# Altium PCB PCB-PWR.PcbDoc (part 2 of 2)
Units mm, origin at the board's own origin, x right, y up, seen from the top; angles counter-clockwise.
Board outline 90 x 60 mm, 4 copper layers (F.Cu, In1.Cu, In2.Cu, B.Cu); 66 components, 31 nets, 210 pads, 267 vias.
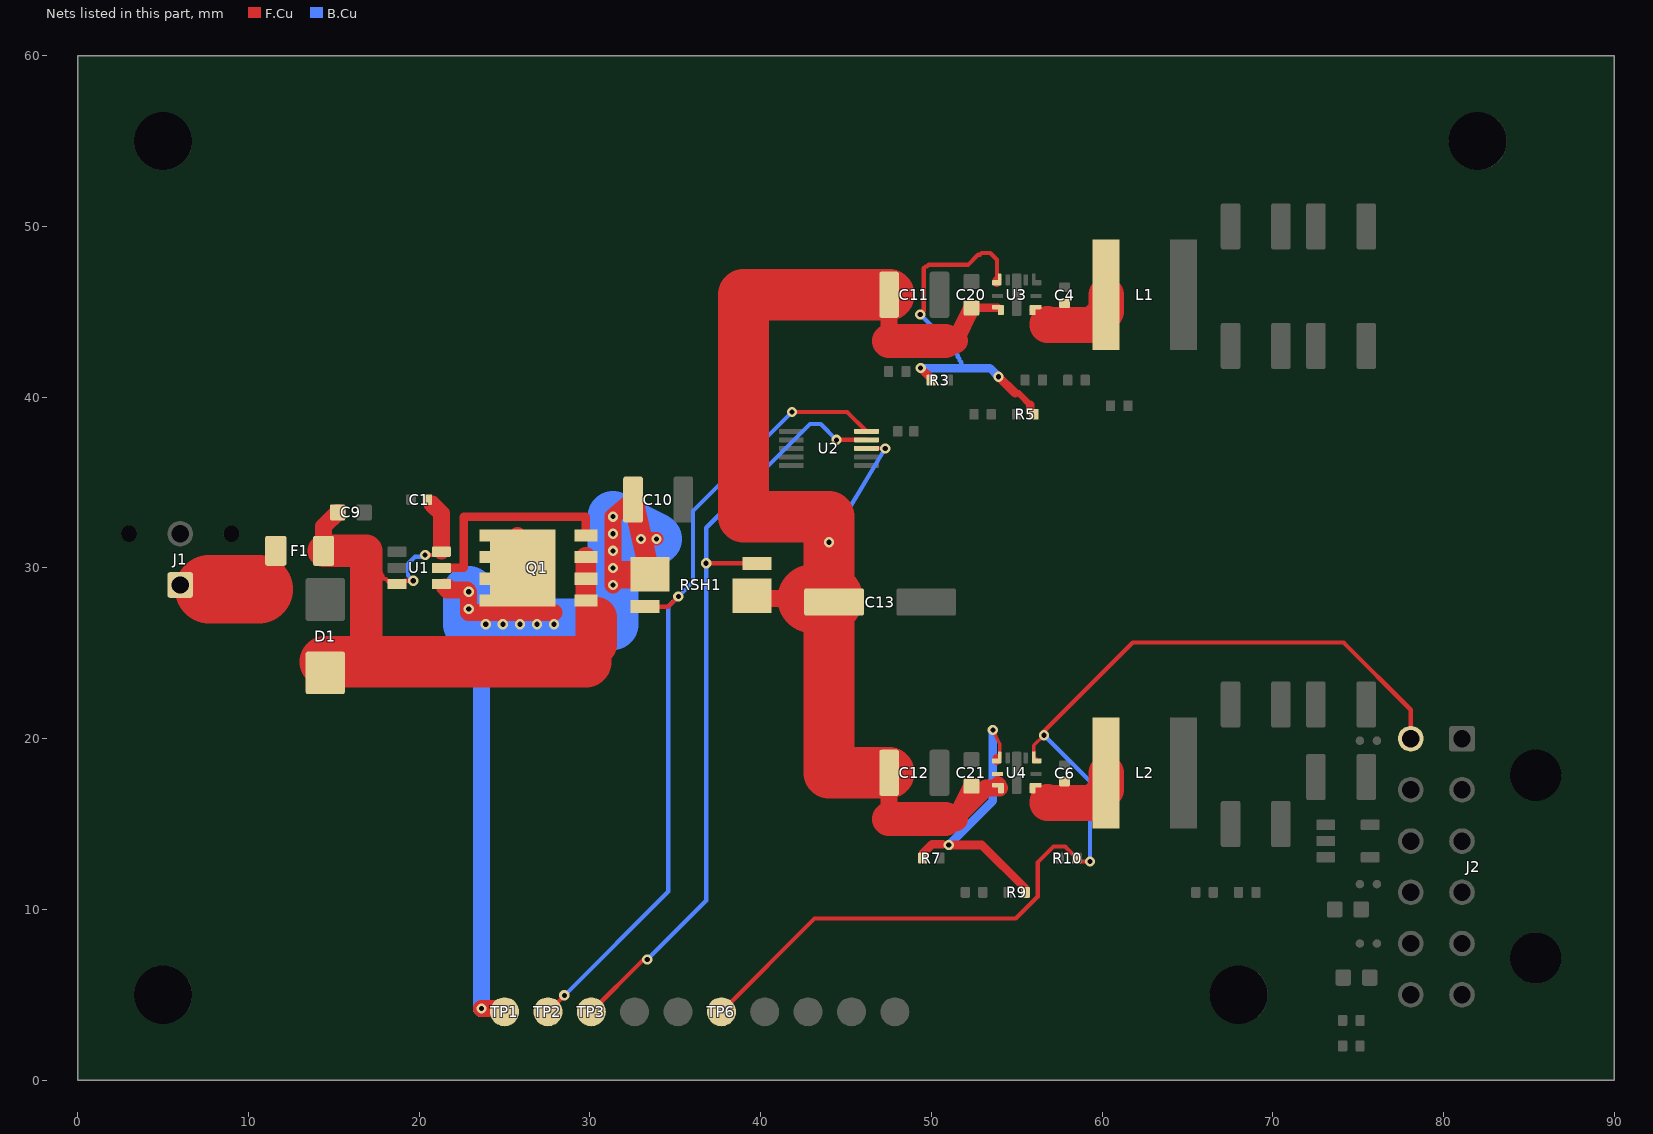
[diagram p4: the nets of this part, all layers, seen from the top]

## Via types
v1: diameter 0.6, hole 0.3, F.Cu to B.Cu, tented both sides, 267 vias

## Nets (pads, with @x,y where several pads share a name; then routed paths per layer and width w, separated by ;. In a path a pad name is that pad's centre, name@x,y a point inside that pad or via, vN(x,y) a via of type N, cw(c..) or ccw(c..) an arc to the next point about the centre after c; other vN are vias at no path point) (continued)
PWR_GOOD: J2.7 R10.2 TP6.1 U4.5 | length 64.7
  F.Cu w0.2: U4.5@56,19.1 56,19.6 v1(56.6,20.2)
  F.Cu w0.201: U4.5@56,19.1 U4.5@56,18.9 56.01,18.9 U4.5@56.112,18.798
  F.Cu w0.25: TP6.1@37.7,4 43.16,9.46 54.944,9.46 56.225,10.741 56.225,12.751 57.149,13.676 57.834,13.676 R10.2@58.51,13 58.71,12.8 v1(59.296,12.8) ; U4.5@56.112,18.798 56.175,18.735 U4.5@56.175,18.7 ; v1(56.6,20.2) 56.6,20.429 61.797,25.627 74.148,25.627 78.08,21.695 J2.7@78.08,20
  B.Cu w0.25: v1(56.6,20.2) 59.296,17.504 v1(59.296,12.8)
REV_GATE: Q1.4 U1.5 | length 12.6
  F.Cu w0.5: U1.5@21.3,30 22.6,30 22.6,33 29.77,33 Q1.4@29.77,31.905
RT_3V3: R7.1 R9.2 U4.8 | length 17.6
  F.Cu w0.2: v1(53.6,20.5) 54,19.7 U4.8@54,19.1
  F.Cu w0.201: 53.825,18.86 53.865,18.9 U4.8@54,18.9 U4.8@54,19.1
  F.Cu w0.375: 50.667,13.81 50.707,13.771 v1(51.018,13.771) v1(51.018,13.771)
  F.Cu w0.5: R7.1@49.49,13 49.49,13.256 50.045,13.81 50.667,13.81 ; v1(51.018,13.771) 52.953,13.771 55.51,11.214 R9.2@55.51,11 ; U4.8@53.825,18.7 53.825,18.86
  B.Cu w0.5: v1(51.018,13.771) 53.6,16.353 v1(53.6,20.5)
RT_3V8: R3.1 R5.2 U3.8 | length 22.1
  F.Cu w0.201: 53.825,46.86 53.865,46.9 U3.8@54,46.9
  F.Cu w0.25: v1(49.35,44.85) 49.55,45.05 49.55,47.55 49.65,47.65 49.75,47.65 49.85,47.75 52.15,47.75 52.75,48.35 52.85,48.35 52.95,48.45 53.45,48.45 53.85,48.05 53.85,46.95
  F.Cu w0.375: 54.909,40.229 55.114,40.229 55.8,39.543
  F.Cu w0.5: v1(49.372,41.705) 49.99,41.088 R3.1@49.99,41 ; U3.8@53.825,46.7 53.825,46.86 ; v1(53.939,41.199) 54.909,40.229 ; 55.8,39.543 55.8,39.21 R5.2@56.01,39
  B.Cu w0.25: v1(49.35,44.85) 51.35,42.85 51.35,42.75 51.45,42.65 51.45,42.55 51.55,42.45 51.55,42.35 51.65,42.25 51.65,42.15 51.75,42.05 51.75,41.85 51.85,41.75
  B.Cu w0.5: v1(49.372,41.705) 53.433,41.705 v1(53.939,41.199)
SHUNT_LOAD_SENSE: RSH1.4 TP3.1 U2.9 | length 46.5
  F.Cu w0.25: TP3.1@30.08,4 33.147,7.067 v1(33.362,7.067) ; v1(36.811,30.27) RSH1.4@39.78,30.27 ; v1(44.45,37.5) U2.9@46.2,37.5
  B.Cu w0.25: v1(33.362,7.067) 36.811,10.516 v1(36.811,30.27) 36.811,32.351 42.887,38.427 43.523,38.427 v1(44.45,37.5)
SHUNT_SOURCE_SENSE: RSH1.3 TP2.1 U2.10 | length 48.1
  F.Cu w0.25: TP2.1@27.54,4 v1(28.504,4.964) ; RSH1.3@33.22,27.73 34.397,27.73 34.59,27.73 v1(35.18,28.32) ; v1(41.841,39.132) 45.067,39.132 U2.10@46.2,38
  B.Cu w0.25: v1(28.504,4.964) 34.59,11.05 34.59,27.73 v1(35.18,28.32) 36.043,29.183 36.043,33.335 v1(41.841,39.132)
SW_3V3: C6.2 L2.1 U4.3 | length 6
  F.Cu w0.251: U4.3@56.086,17.013 56.75,16.35
  F.Cu w0.346: U4.3@55.927,17.1 56,17.1 U4.3@56.086,17.013
  F.Cu w0.561: 56.75,16.349 56.8,16.3
  F.Cu w2.1: 56.8,16.3 56.8,16.22 59.45,16.22 60.24,17.01 L2.1@60.24,18
SW_3V8: C4.2 L1.1 U3.3 | length 6
  F.Cu w0.251: U3.3@56.086,45.013 56.75,44.35
  F.Cu w0.346: U3.3@55.927,45.1 56,45.1 U3.3@56.086,45.013
  F.Cu w0.561: 56.75,44.349 56.8,44.3
  F.Cu w2.1: 56.8,44.3 56.8,44.22 59.45,44.22 60.24,45.01 L1.1@60.24,46
VBAT_FUSED: C1.2 C9.1 D1.1 F1.2 Q1.1 Q1.2 Q1.3 U1.3 U1.6 | length 45.9
  F.Cu w0.25: 17.25,30.25 17.75,29.75 17.75,29.65 17.85,29.55 17.85,29.45 17.95,29.35 18.05,29.35 18.25,29.15 U1.3@18.35,29.15 ; U1.3@19.05,29.15 19.15,29.25 v1(19.65,29.25) ; v1(20.35,30.75) 20.85,30.75 U1.6@20.95,30.85
  F.Cu w0.561: C1.2@20.48,34 C1.2@20.749,33.731
  F.Cu w0.601: U1.6@21.3,30.95 U1.6@21.3,31.002
  F.Cu w1: F1.2@14.4,31 14.4,32.425 C9.1@15.225,33.25 ; D1.1@14.5,23.85 15.15,24.5 16.9,24.5 ; C1.2@20.749,33.731 21.3,33.18 U1.6@21.3,31.002
  F.Cu w1.2: 29.77,24.5 Q1.3@29.77,30.635
  F.Cu w1.9: F1.2@14.4,31 16.9,31 16.9,24.5
  F.Cu w2.4: 30.4,25.5 30.4,27.1
  F.Cu w3: D1.1@14.5,24.5 29.77,24.5
  B.Cu w0.25: v1(19.65,29.25) 19.35,29.55 19.35,30.25 19.75,30.65 20.25,30.65 v1(20.35,30.75)
VBAT_PROTECTED: C10.1 Q1.5 Q1.6 Q1.7 Q1.8 RSH1.1 TP1.1 U1.4 | length 70.8
  F.Cu w0.601: U1.4@21.3,29.05 U1.4@21.471,28.879 ; 21.643,28.707 U1.4@21.643,28.879
  F.Cu w0.8: v1(33,31.7) v1(33.9,31.7)
  F.Cu w1: U1.4@21.471,28.879 U1.4@21.643,28.879 ; 21.643,28.707 22.793,28.707 v1(22.9,28.6) 22.9,27.4 27.9,27.4 ; v1(23.646,4.2) 24.8,4.2 TP1.1@25,4 ; Q1.8@25.764,28.095 25.764,28.435 Q1.5@26.059,28.73 26.059,29.07 Q1.7@25.764,29.365 25.764,29.705 Q1.5@26.059,30 25.764,30.295 Q1.6@25.764,30.635 26.059,30.93 Q1.5@26.059,31.27 25.764,31.565 Q1.5@25.764,31.905 ; v1(31.35,29) v1(31.35,33) C10.1@32.525,34 ; v1(31.35,30) v1(31.35,31) ; RSH1.1@32.6,29.6 33.48,29.6 RSH1.1@33.515,29.635
  F.Cu w1.2: C10.1@32.525,34 RSH1.1@33.515,29.635
  F.Cu w1.6: 31.85,29.6 RSH1.1@32.6,29.6
  B.Cu w1: v1(23.646,4.2) 23.646,26.446 v1(23.9,26.7) ; v1(31.35,31) v1(31.35,32)
  B.Cu w3: v1(22.9,28.6) 22.9,26.7 31.35,26.7 v1(31.35,33) v1(33.9,31.7)
  other v1: 24.9,26.7 25.9,26.7 26.9,26.7 27.9,26.7 22.9,27.6
VBAT_RAW: F1.1 J1.1 | length 7.4
  F.Cu w1: J1.1@6,29 6.25,28.75 7.7,28.75 ; 10.6,28.75 11.6,29.75 F1.1@11.6,31
  F.Cu w4: 7.7,28.75 10.6,28.75
VBAT_SYS: C11.1 C12.1 C13.1 C20.1 C21.1 RSH1.2 U2.8 U3.1 U4.1 U4.9 | length 82.6
  F.Cu w0.2: U2.8@46.2,37 v1(47.3,37)
  F.Cu w0.25: U4.9@53.875,17.925 U4.1@53.9,17.25
  F.Cu w0.251: U3.1@53.897,45.275 U3.1@54.073,45.1
  F.Cu w0.346: U4.1@53.998,17.1 U4.1@54.073,17.1
  F.Cu w0.5: C21.1@52.35,17.225 U4.1@53.9,17.25 ; C20.1@52.35,45.225 U3.1@53.9,45.25
  F.Cu w1: RSH1.2@39.485,28.365 39.65,28.2 40,28.2 C13.1@43,28.2 ; C13.1@44,28.2 44.2,28 C13.1@44.3,28 ; 47.525,15.3 C12.1@47.525,18 ; 47.525,43.3 C11.1@47.525,46 ; 51.4,43.3 C20.1@52.35,45.225 ; C21.1@52.35,17.225 51.4,15.3 53.2,17.1 53.897,17.1 ; U4.1@53.897,17.275 53.897,17.1 ; U4.1@53.998,17.1 53.897,17.1
  F.Cu w1.5: 50.8,15.3 51.4,15.3 ; 50.8,43.3 51.4,43.3
  F.Cu w2: 47.525,15.3 50.8,15.3 ; 47.525,43.3 50.8,43.3
  F.Cu w3: C12.1@47.525,18 44,18 44,28.2 44,33 39,33 39,46 C11.1@47.525,46
  F.Cu w4: C13.1@43,28.2 C13.1@44,28.2
  B.Cu w0.25: v1(44,31.5) v1(47.3,37)
pads on no net: H1.Un1 H2.Un1 H3.Un1 H4.Un1 J1.Un1 J1.Un2 J2.Un1 J2.Un2 Q1.Un1 Q1.Un2 Q1.Un3 Q1.Un4 Q1.Un5 Q1.Un6 Q1.Un7 Q1.Un8 Q1.Un9 Q1.Un10 Q1.Un11 Q1.Un12 Q1.Un13 Q1.Un14 Q1.Un15 Q1.Un16 U3.Un1 U3.Un2 U3.Un3 U3.Un4 U3.Un5 U3.Un6 U3.Un7 U4.Un1 U4.Un2 U4.Un3 U4.Un4 U4.Un5 U4.Un6 U4.Un7 U5.4

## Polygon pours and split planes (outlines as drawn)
GND_PWR on F.Cu "F.Cu-GND_PWR" (solid, remove dead copper, pour order 52): 0.45,59.55 89.55,59.55 89.55,0.45 0.45,0.45
GND_MODEM on F.Cu "F.Cu-GND_MODEM" (solid, remove dead copper, pour order 42): 73.603,20.483 73.227,19.957 73.079,19.543 73.05,19.25 73.05,18.195 72.879,17.743 72.85,17.45 72.879,17.157 72.964,16.876 73.103,16.617 73.289,16.389 73.517,16.203 73.776,16.064 74.057,15.979 74.35,15.95 74.643,15.979 75.057,16.127 75.302,16.29 75.71,16.698 75.936,17.076 76.043,17.503 76.05,18.653 76.373,19.143 76.485,19.415 76.55,19.85 76.521,20.143 76.436,20.424 76.297,20.683 76.002,21.009 75.624,21.236 75.197,21.343 74.757,21.321 74.343,21.173 73.989,20.911
GND_DIGITAL on F.Cu "F.Cu-GND_DIGITAL" (solid, remove dead copper, pour order 40): 75.8,13.6 82.6,13.6 82.6,9.6 75.8,9.6
VBAT_RAW on F.Cu "F.Cu-VBAT_RAW" (solid, remove dead copper, pour order 48): 13.146,28.481 13.448,28.985 13.59,29.554 13.6,31 13.514,31.581 13.263,32.111 12.869,32.546 12.365,32.848 11.796,32.99 11.404,32.99 11.019,32.914 10.657,32.764 10.186,32.414 9.836,31.943 9.686,31.581 9.61,31.196 9.6,30.75 6.966,30.75 6.581,30.914 6,31 5.419,30.914 4.889,30.663 4.454,30.269 4.152,29.765 4.01,29.196 4.01,28.804 4.086,28.419 4.236,28.057 4.454,27.731 4.836,27.336 5.139,27.087 5.669,26.836 6.054,26.76 10.6,26.75 10.99,26.788 11.543,26.986 11.869,27.204
VBAT_SYS on F.Cu "F.Cu-VBAT_SYS-1" (solid, remove dead copper, pour order 51): 152 vertices, not listed, extent 37,13.3 56.072,48
3V3_DIGITAL on F.Cu "F.Cu-3V3_DIGITAL-3" (solid, remove dead copper, pour order 36): 49.447,38.633 49.261,38.861 49.033,39.047 48.635,39.235 48.347,39.293 48.053,39.293 47.765,39.235 47.493,39.123 47.248,38.96 47.041,38.752 46.814,38.374 46.707,37.947 46.7,37.5 46.053,37.493 45.626,37.386 45.367,37.247 45.139,37.061 44.877,36.707 44.729,36.293 44.707,35.853 44.814,35.426 45.04,35.048 45.248,34.84 45.493,34.677 45.765,34.565 46.053,34.507 47.847,34.507 48.274,34.614 48.652,34.84 49.359,35.548 49.586,35.926 49.671,36.207 49.7,36.5 49.693,37.947 49.586,38.374
3V8_MODEM on F.Cu "F.Cu-3V8_MODEM-1" (solid, remove dead copper, pour order 39): 49.029,9.425 48.757,9.537 48.322,9.602 47.15,9.602 46.714,9.537 46.316,9.349 45.99,9.053 45.764,8.676 45.678,8.394 45.657,7.955 45.764,7.528 45.99,7.15 46.198,6.942 46.576,6.716 46.857,6.63 47.7,6.602 47.912,6.39 47.895,3.948 34.793,3.948 33.681,5.061 33.453,5.247 33.055,5.435 32.62,5.5 32.185,5.435 31.913,5.323 31.668,5.159 31.373,4.833 31.185,4.435 31.127,4.147 31.127,3.853 31.185,3.565 31.297,3.293 31.461,3.048 33.111,1.387 33.339,1.201 33.598,1.062 34.025,0.955 48.516,0.948 48.952,1.012 49.224,1.125 49.468,1.288 50.571,2.392 50.798,2.769 50.883,3.051 50.912,3.343 50.912,7.012 50.847,7.447 50.659,7.845 50.472,8.072 49.382,9.162
VBAT_FUSED on F.Cu "F.Cu-VBAT_FUSED" (solid, remove dead copper, pour order 44): 12.552,33.19 12.41,32.621 12.4,31 12.438,30.61 12.636,30.057 12.854,29.731 13.131,29.454 13.635,29.152 14.204,29.01 14.9,29 14.9,26.5 14.11,26.462 13.735,26.348 13.389,26.163 13.086,25.914 12.837,25.611 12.652,25.265 12.538,24.89 12.5,24.5 12.529,24.175 12.51,23.654 12.652,23.085 12.837,22.739 13.086,22.436 13.389,22.187 13.735,22.002 14.304,21.86 14.89,21.888 15.443,22.086 15.769,22.304 15.978,22.5 29.966,22.51 30.351,22.586 30.713,22.736 31.184,23.086 31.534,23.557 31.699,23.982 32.063,24.389 32.248,24.735 32.39,25.304 32.39,27.296 32.314,27.681 32.164,28.043 31.946,28.369 31.77,28.554 31.77,30.635 31.732,31.025 31.534,31.578 31.316,31.904 30.881,32.298 30.535,32.483 30.16,32.597 29.77,32.635 29.38,32.597 29.005,32.483 28.659,32.298 28.356,32.049 28.107,31.746 27.922,31.4 27.808,31.025 27.77,30.635 27.77,26.5 18.9,26.5 18.9,27.157 19.246,27.16 19.672,27.251 20.04,27.288 20.415,27.402 20.761,27.587 21.064,27.836 21.313,28.139 21.498,28.485 21.618,28.903 22.243,29.186 22.569,29.404 22.846,29.681 23.148,30.185 23.262,30.56 23.3,30.95 23.29,33.376 23.214,33.761 23.064,34.123 22.714,34.594 21.749,35.546 21.423,35.764 21.061,35.914 20.676,35.99 20.284,35.99 19.899,35.914 19.369,35.663 19.066,35.414 18.817,35.111 18.632,34.765 18.518,34.39 18.49,33.804 18.632,33.235 18.817,32.889 19.239,32.413 18.936,32.164 18.697,31.874 18.446,32.269 18.011,32.663 17.665,32.848 17.204,32.974 17.215,33.446 17.139,33.831 16.888,34.361 16.639,34.664 16.168,35.014 15.615,35.212 15.225,35.25 14.835,35.212 14.46,35.098 14.114,34.913 13.811,34.664 12.986,33.839 12.737,33.536
3V3_DIGITAL on F.Cu "F.Cu-3V3_DIGITAL-2" (solid, remove dead copper, pour order 35): 56.832,21.633 56.537,21.959 56.159,22.186 55.732,22.293 55.438,22.293 55.011,22.186 54.633,21.959 54.425,21.752 54.199,21.374 54.114,21.093 54.085,20.8 54.085,18.875 54.114,18.582 54.199,18.301 54.425,17.923 54.633,17.715 55.011,17.489 55.292,17.404 55.585,17.375 55.878,17.404 56.159,17.489 56.418,17.628 56.646,17.814 56.832,18.042 56.971,18.301 57.056,18.582 57.085,18.875 57.085,20.8 57.02,21.235
3V3_DIGITAL on F.Cu "F.Cu-3V3_DIGITAL-1" (solid, remove dead copper, pour order 34): 207 vertices, not listed, extent 55.99,0.507 75.59,26.493
VBAT_PROTECTED on F.Cu "F.Cu-VBAT_PROTECTED-1" (solid, remove dead copper, pour order 47): 26.069,5.746 25.743,5.964 25.381,6.114 24.8,6.2 23.646,6.2 23.256,6.162 22.881,6.048 22.535,5.863 22.232,5.614 21.983,5.311 21.798,4.965 21.684,4.59 21.646,4.2 21.684,3.81 21.798,3.435 21.983,3.089 22.232,2.786 22.535,2.537 22.881,2.352 23.256,2.238 23.646,2.2 24.133,2.2 24.61,2.038 25,2 25.581,2.086 26.111,2.337 26.546,2.731 26.764,3.057 26.914,3.419 27,4 26.914,4.581 26.764,4.943 26.546,5.269
VBAT_PROTECTED on F.Cu "F.Cu-VBAT_PROTECTED" (solid, remove dead copper, pour order 46): 27.427,33.016 27.178,33.319 26.875,33.568 26.345,33.819 25.764,33.905 25.183,33.819 24.821,33.669 24.35,33.319 24.101,33.016 23.916,32.67 23.774,32.101 23.764,31.565 23.821,31.1 23.774,30.831 23.764,30.454 23.558,30.555 23.183,30.669 22.449,30.707 21.881,30.964 21.496,31.04 21.104,31.04 20.719,30.964 20.189,30.713 19.886,30.464 19.637,30.161 19.452,29.815 19.338,29.44 19.3,29.05 19.338,28.66 19.452,28.285 19.637,27.939 19.886,27.636 20.374,27.161 20.7,26.943 20.986,26.821 21.136,26.457 21.486,25.986 21.957,25.636 22.319,25.486 22.9,25.4 27.9,25.4 28.29,25.438 28.665,25.552 29.011,25.737 29.446,26.131 29.664,26.457 29.814,26.819 29.89,27.204 29.883,27.644 30.239,27.337 30.769,27.086 31.35,27 31.74,27.038 32.293,27.236 32.619,27.454 32.777,27.6 33.676,27.61 34.245,27.752 34.591,27.937 34.894,28.186 35.094,28.408 35.279,28.692 35.444,29.106 35.51,29.492 35.499,29.884 35.397,30.377 35.664,30.757 35.862,31.31 35.9,31.7 35.814,32.281 35.664,32.643 35.446,32.969 35.169,33.246 34.68,33.541 34.428,34.615 34.352,34.814 34.168,35.141 33.901,35.451 33.436,35.78 33.071,35.924 32.668,35.995 32.1,35.954 31.711,35.827 31.229,35.523 30.054,34.523 29.781,34.241 29.586,33.943 29.436,33.581 29.356,33.16 29.367,28.756 29.169,28.946 28.843,29.164 28.481,29.314 28.03,29.394 28.002,29.535 28.059,30 28.002,30.465 28.049,30.734 28.059,31.27 28.021,31.66 27.907,32.035 27.695,32.418 27.612,32.67
3V8_MODEM on F.Cu "F.Cu-3V8_MODEM" (solid, remove dead copper, pour order 38): 152 vertices, not listed, extent 54.05,18.507 85,54.7
VBAT_SYS on F.Cu "F.Cu-VBAT_SYS" (solid, remove dead copper, pour order 50): 48.243,35.236 48.569,35.454 48.963,35.889 49.214,36.419 49.29,36.804 49.262,37.39 49.148,37.765 48.846,38.269 48.569,38.546 48.065,38.848 47.69,38.962 47.3,39 46.004,38.99 45.619,38.914 45.257,38.764 44.931,38.546 44.654,38.269 44.436,37.943 44.286,37.581 44.21,37.196 44.21,36.804 44.286,36.419 44.436,36.057 44.654,35.731 44.931,35.454 45.435,35.152 46.004,35.01 47.496,35.01 47.881,35.086
3V3_DIGITAL on F.Cu "F.Cu-3V3_DIGITAL" (solid, remove dead copper, pour order 33): 62.833,40.207 62.669,40.452 62.343,40.747 61.945,40.935 61.657,40.993 61.363,40.993 60.936,40.886 60.677,40.747 60.35,40.452 60.124,40.074 60.039,39.793 60.01,39.5 60.017,38.453 60.075,38.165 60.187,37.893 60.35,37.648 60.558,37.44 60.803,37.277 61.075,37.165 61.363,37.107 61.657,37.107 61.945,37.165 62.217,37.277 62.462,37.44 62.669,37.648 62.896,38.026 63.003,38.453 63.003,39.647 62.945,39.935
VBAT_FUSED on B.Cu "B.Cu-VBAT_FUSED" (solid, remove dead copper, pour order 43): 21.664,29.236 22.013,29.639 22.264,30.169 22.35,30.75 22.312,31.14 22.114,31.693 21.896,32.019 21.461,32.413 21.115,32.598 20.74,32.712 20.35,32.75 19.36,32.612 18.985,32.498 18.481,32.196 17.936,31.664 17.687,31.361 17.502,31.015 17.388,30.64 17.35,30.25 17.36,29.354 17.502,28.785 17.687,28.439 17.936,28.136 18.381,27.704 18.885,27.402 19.454,27.26 19.846,27.26 20.415,27.402 20.761,27.587 21.064,27.836 21.414,28.307 21.564,28.669
3V3_DIGITAL on B.Cu "B.Cu-3V3_DIGITAL-2" (solid, remove dead copper, pour order 32): 84.421,22.293 84.336,22.574 84.197,22.833 83.902,23.159 83.524,23.386 83.097,23.493 76.5,23.5 76.207,23.471 75.866,23.359 71.366,21.259 71.113,21.109 70.894,20.913 70.647,20.548 70.517,20.128 70.515,19.688 70.641,19.266 70.791,19.013 70.987,18.794 71.222,18.617 71.487,18.49 71.772,18.417 72.066,18.401 72.357,18.443 72.634,18.541 76.833,20.5 81.45,20.5 81.45,16.22 80.141,15.17 79.931,14.964 79.701,14.589 79.612,14.309 79.58,14.017 79.606,13.724 79.688,13.441 79.91,13.061 80.115,12.851 80.49,12.621 80.771,12.532 81.063,12.5 81.356,12.526 81.639,12.608 81.899,12.744 83.902,14.34 84.197,14.667 84.38,15.049 84.45,15.483 84.45,22
3V8_MODEM on B.Cu "B.Cu-3V8_MODEM" (solid, remove dead copper, pour order 37): 65.574,24.158 65.16,24.01 64.898,23.831 53.326,23.831 53.034,23.802 52.753,23.717 52.375,23.49 46.089,17.215 45.902,16.987 45.764,16.728 45.678,16.447 45.65,16.154 45.65,8.102 45.678,7.809 45.764,7.528 45.99,7.15 46.198,6.942 46.576,6.716 47.003,6.609 47.297,6.609 47.724,6.716 47.983,6.854 48.309,7.15 48.472,7.395 48.585,7.666 48.65,8.102 48.65,15.533 53.948,20.831 65.51,20.831 65.946,20.896 66.24,21.022 69.906,17.367 70.15,17.204 70.422,17.091 70.857,17.026 79.607,17.026 79.899,17.055 80.314,17.204 80.667,17.466 82.24,19.048 82.403,19.293 82.515,19.565 82.58,20 82.551,20.293 82.466,20.574 82.24,20.952 82.032,21.16 81.654,21.386 81.373,21.471 81.08,21.5 80.645,21.435 80.247,21.247 80.019,21.061 78.985,20.027 71.479,20.027 67.757,23.748 67.53,23.934 67.27,24.073 66.843,24.18 65.867,24.187
VBAT_SYS on B.Cu "B.Cu-VBAT_SYS" (solid, remove dead copper, pour order 49): 42.285,32.529 42.06,31.987 42.002,31.599 42.022,31.207 42.192,30.646 42.393,30.309 42.656,30.019 42.971,29.785 43.325,29.617 43.706,29.522 44.097,29.502 44.673,29.617 45.027,29.784 45.342,30.017 45.715,30.471 49.015,35.971 49.183,36.325 49.298,36.901 49.24,37.485 49.108,37.854 48.783,38.342 48.492,38.606 48.156,38.808 47.787,38.94 47.399,38.997 47.007,38.978 46.627,38.883 46.273,38.716 45.958,38.482 45.585,38.029
VBAT_PROTECTED on B.Cu "B.Cu-VBAT_PROTECTED" (solid, remove dead copper, pour order 45): 33.548,29.731 34.135,29.714 34.518,29.798 35.043,30.059 35.47,30.461 35.762,30.971 35.869,31.348 35.886,31.935 35.733,32.501 35.421,32.999 35.138,33.27 34.808,33.482 32.115,34.848 31.74,34.962 31.311,35 30.96,34.962 30.732,34.902 30.407,34.764 30.207,34.641 29.936,34.414 29.78,34.238 29.568,33.908 29.436,33.581 29.381,33.352 29.35,33 29.35,28.7 24.895,28.7 24.862,28.99 24.748,29.365 24.563,29.711 24.314,30.014 23.843,30.364 23.481,30.514 23.096,30.59 22.51,30.562 21.957,30.364 21.486,30.014 21.237,29.711 21.052,29.365 20.91,28.796 20.91,26.504 20.986,26.119 21.136,25.757 21.354,25.431 21.646,25.143 21.656,4.004 21.798,3.435 22.1,2.931 22.377,2.654 22.881,2.352 23.45,2.21 23.842,2.21 24.227,2.286 24.757,2.537 25.192,2.931 25.41,3.257 25.56,3.619 25.636,4.004 25.646,24.7 31.546,24.71 31.931,24.786 32.461,25.037 32.764,25.286 33.013,25.589 33.198,25.935 33.312,26.31 33.35,26.7 33.35,29.777
GND_PWR on B.Cu "B.Cu-GND_PWR" (solid, remove dead copper, pour order 53): 0.45,59.55 89.55,59.55 89.55,0.45 0.45,0.45
GND_MODEM on B.Cu "B.Cu-GND_MODEM" (solid, remove dead copper, pour order 41): 76.624,18.836 76.197,18.943 74.35,18.95 73.915,18.885 73.517,18.697 73.289,18.511 73.103,18.283 72.964,18.024 72.879,17.743 72.85,17.45 72.879,17.157 72.964,16.876 73.103,16.617 73.398,16.29 73.643,16.127 73.915,16.015 74.35,15.95 75.429,15.95 76.389,14.989 76.617,14.803 77.076,14.564 77.515,14.415 77.803,14.357 78.797,14.357 79.224,14.464 79.811,14.76 80.257,14.927 81.257,15.427 81.611,15.689 81.873,16.043 81.985,16.315 82.043,16.603 82.043,16.897 81.985,17.185 81.873,17.457 81.709,17.702 81.502,17.909 81.257,18.073 80.985,18.185 80.697,18.243 80.157,18.221 79.876,18.136 79.089,17.74 78.776,17.636 78.275,17.388 78.219,17.402 77.002,18.61
3V3_DIGITAL on B.Cu "B.Cu-3V3_DIGITAL-1" (solid, remove dead copper, pour order 31): 56.259,11.243 56.561,10.922 56.808,10.764 57.082,10.656 57.372,10.605 57.666,10.61 58.091,10.726 58.464,10.959 58.753,11.291 58.933,11.692 58.985,11.982 58.98,12.276 57.012,21.263 56.894,21.532 56.726,21.774 56.394,22.063 55.993,22.243 55.703,22.295 55.409,22.29 55.122,22.227 54.853,22.109 54.611,21.941 54.407,21.729 54.249,21.481 54.141,21.208 54.09,20.918 54.095,20.624 56.025,11.779 56.116,11.499
3V3_DIGITAL on B.Cu "B.Cu-3V3_DIGITAL" (solid, remove dead copper, pour order 30): 62.945,39.035 62.833,39.307 62.669,39.552 62.343,39.847 62.084,39.986 61.657,40.093 61.363,40.093 61.075,40.035 60.803,39.923 60.558,39.759 60.35,39.552 60.187,39.307 60.075,39.035 60.01,38.6 60.01,37.5 47.7,37.5 47.407,37.471 47.126,37.386 46.867,37.247 46.639,37.061 46.453,36.833 46.314,36.574 46.229,36.293 46.2,36 46.229,35.707 46.377,35.293 46.639,34.939 46.993,34.677 47.265,34.565 47.553,34.507 60.887,34.5 63,32.38 63,25 63.065,24.565 63.253,24.167 63.439,23.939 63.667,23.753 63.926,23.614 64.207,23.529 64.5,23.5 64.793,23.529 65.074,23.614 65.333,23.753 65.659,24.048 65.886,24.426 65.993,24.853 65.993,33.147 65.886,33.574 65.659,33.952 63.01,36.62 63.01,38.6
GND_PWR on In1.Cu "In1.Cu-GND_PWR-2" (solid, remove dead copper, pour order 29): 49.8,47.6 55.35,47.6 55.35,44.4 49.8,44.4
GND_PWR on In1.Cu "In1.Cu-GND_PWR-1" (solid, remove dead copper, pour order 28): 49.8,19.6 55.35,19.6 55.35,16.4 49.8,16.4
GND_PWR on In1.Cu "In1.Cu-GND_PWR" (solid, remove dead copper, pour order 54): 0.45,59.55 89.55,59.55 89.55,0.45 0.45,0.45
GND_PWR on In2.Cu "In2.Cu-GND_PWR" (solid, remove dead copper, pour order 55): 0.45,59.55 89.55,59.55 89.55,0.45 0.45,0.45

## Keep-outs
F.Cu:
  region: 82.78,58.923 83.531,58.696 84.222,58.326 84.828,57.828 85.326,57.222 85.696,56.531 85.923,55.78 86,55 85.923,54.22 85.696,53.469 85.326,52.778 84.828,52.172 84.222,51.674 83.531,51.304 82.78,51.077 82,51 81.22,51.077 80.469,51.304 79.778,51.674 79.172,52.172 78.674,52.778 78.304,53.469 78.077,54.22 78,55 78.077,55.78 78.304,56.531 78.674,57.222 79.172,57.828 79.778,58.326 80.469,58.696 81.22,58.923 82,59
  region: 5.78,8.923 6.531,8.696 7.222,8.326 7.828,7.828 8.326,7.222 8.696,6.531 8.923,5.78 9,5 8.923,4.22 8.696,3.469 8.326,2.778 7.828,2.172 7.222,1.674 6.531,1.304 5.78,1.077 5,1 4.22,1.077 3.469,1.304 2.778,1.674 2.172,2.172 1.674,2.778 1.304,3.469 1.077,4.22 1,5 1.077,5.78 1.304,6.531 1.674,7.222 2.172,7.828 2.778,8.326 3.469,8.696 4.22,8.923 5,9
  region: 68.78,8.923 69.531,8.696 70.222,8.326 70.828,7.828 71.326,7.222 71.696,6.531 71.923,5.78 72,5 71.923,4.22 71.696,3.469 71.326,2.778 70.828,2.172 70.222,1.674 69.531,1.304 68.78,1.077 68,1 67.22,1.077 66.469,1.304 65.778,1.674 65.172,2.172 64.674,2.778 64.304,3.469 64.077,4.22 64,5 64.077,5.78 64.304,6.531 64.674,7.222 65.172,7.828 65.778,8.326 66.469,8.696 67.22,8.923 68,9
  region: 5.78,58.923 6.531,58.696 7.222,58.326 7.828,57.828 8.326,57.222 8.696,56.531 8.923,55.78 9,55 8.923,54.22 8.696,53.469 8.326,52.778 7.828,52.172 7.222,51.674 6.531,51.304 5.78,51.077 5,51 4.22,51.077 3.469,51.304 2.778,51.674 2.172,52.172 1.674,52.778 1.304,53.469 1.077,54.22 1,55 1.077,55.78 1.304,56.531 1.674,57.222 2.172,57.828 2.778,58.326 3.469,58.696 4.22,58.923 5,59
  region: 76.1,10.78 75.1,10.78 75.1,11.18 76.1,11.18
In1.Cu:
  region: 82.78,58.923 83.531,58.696 84.222,58.326 84.828,57.828 85.326,57.222 85.696,56.531 85.923,55.78 86,55 85.923,54.22 85.696,53.469 85.326,52.778 84.828,52.172 84.222,51.674 83.531,51.304 82.78,51.077 82,51 81.22,51.077 80.469,51.304 79.778,51.674 79.172,52.172 78.674,52.778 78.304,53.469 78.077,54.22 78,55 78.077,55.78 78.304,56.531 78.674,57.222 79.172,57.828 79.778,58.326 80.469,58.696 81.22,58.923 82,59
  region: 5.78,8.923 6.531,8.696 7.222,8.326 7.828,7.828 8.326,7.222 8.696,6.531 8.923,5.78 9,5 8.923,4.22 8.696,3.469 8.326,2.778 7.828,2.172 7.222,1.674 6.531,1.304 5.78,1.077 5,1 4.22,1.077 3.469,1.304 2.778,1.674 2.172,2.172 1.674,2.778 1.304,3.469 1.077,4.22 1,5 1.077,5.78 1.304,6.531 1.674,7.222 2.172,7.828 2.778,8.326 3.469,8.696 4.22,8.923 5,9
  region: 68.78,8.923 69.531,8.696 70.222,8.326 70.828,7.828 71.326,7.222 71.696,6.531 71.923,5.78 72,5 71.923,4.22 71.696,3.469 71.326,2.778 70.828,2.172 70.222,1.674 69.531,1.304 68.78,1.077 68,1 67.22,1.077 66.469,1.304 65.778,1.674 65.172,2.172 64.674,2.778 64.304,3.469 64.077,4.22 64,5 64.077,5.78 64.304,6.531 64.674,7.222 65.172,7.828 65.778,8.326 66.469,8.696 67.22,8.923 68,9
  region: 5.78,58.923 6.531,58.696 7.222,58.326 7.828,57.828 8.326,57.222 8.696,56.531 8.923,55.78 9,55 8.923,54.22 8.696,53.469 8.326,52.778 7.828,52.172 7.222,51.674 6.531,51.304 5.78,51.077 5,51 4.22,51.077 3.469,51.304 2.778,51.674 2.172,52.172 1.674,52.778 1.304,53.469 1.077,54.22 1,55 1.077,55.78 1.304,56.531 1.674,57.222 2.172,57.828 2.778,58.326 3.469,58.696 4.22,58.923 5,59
In2.Cu:
  region: 82.78,58.923 83.531,58.696 84.222,58.326 84.828,57.828 85.326,57.222 85.696,56.531 85.923,55.78 86,55 85.923,54.22 85.696,53.469 85.326,52.778 84.828,52.172 84.222,51.674 83.531,51.304 82.78,51.077 82,51 81.22,51.077 80.469,51.304 79.778,51.674 79.172,52.172 78.674,52.778 78.304,53.469 78.077,54.22 78,55 78.077,55.78 78.304,56.531 78.674,57.222 79.172,57.828 79.778,58.326 80.469,58.696 81.22,58.923 82,59
  region: 5.78,8.923 6.531,8.696 7.222,8.326 7.828,7.828 8.326,7.222 8.696,6.531 8.923,5.78 9,5 8.923,4.22 8.696,3.469 8.326,2.778 7.828,2.172 7.222,1.674 6.531,1.304 5.78,1.077 5,1 4.22,1.077 3.469,1.304 2.778,1.674 2.172,2.172 1.674,2.778 1.304,3.469 1.077,4.22 1,5 1.077,5.78 1.304,6.531 1.674,7.222 2.172,7.828 2.778,8.326 3.469,8.696 4.22,8.923 5,9
  region: 68.78,8.923 69.531,8.696 70.222,8.326 70.828,7.828 71.326,7.222 71.696,6.531 71.923,5.78 72,5 71.923,4.22 71.696,3.469 71.326,2.778 70.828,2.172 70.222,1.674 69.531,1.304 68.78,1.077 68,1 67.22,1.077 66.469,1.304 65.778,1.674 65.172,2.172 64.674,2.778 64.304,3.469 64.077,4.22 64,5 64.077,5.78 64.304,6.531 64.674,7.222 65.172,7.828 65.778,8.326 66.469,8.696 67.22,8.923 68,9
  region: 5.78,58.923 6.531,58.696 7.222,58.326 7.828,57.828 8.326,57.222 8.696,56.531 8.923,55.78 9,55 8.923,54.22 8.696,53.469 8.326,52.778 7.828,52.172 7.222,51.674 6.531,51.304 5.78,51.077 5,51 4.22,51.077 3.469,51.304 2.778,51.674 2.172,52.172 1.674,52.778 1.304,53.469 1.077,54.22 1,55 1.077,55.78 1.304,56.531 1.674,57.222 2.172,57.828 2.778,58.326 3.469,58.696 4.22,58.923 5,59
B.Cu:
  region: 82.78,58.923 83.531,58.696 84.222,58.326 84.828,57.828 85.326,57.222 85.696,56.531 85.923,55.78 86,55 85.923,54.22 85.696,53.469 85.326,52.778 84.828,52.172 84.222,51.674 83.531,51.304 82.78,51.077 82,51 81.22,51.077 80.469,51.304 79.778,51.674 79.172,52.172 78.674,52.778 78.304,53.469 78.077,54.22 78,55 78.077,55.78 78.304,56.531 78.674,57.222 79.172,57.828 79.778,58.326 80.469,58.696 81.22,58.923 82,59
  region: 5.78,8.923 6.531,8.696 7.222,8.326 7.828,7.828 8.326,7.222 8.696,6.531 8.923,5.78 9,5 8.923,4.22 8.696,3.469 8.326,2.778 7.828,2.172 7.222,1.674 6.531,1.304 5.78,1.077 5,1 4.22,1.077 3.469,1.304 2.778,1.674 2.172,2.172 1.674,2.778 1.304,3.469 1.077,4.22 1,5 1.077,5.78 1.304,6.531 1.674,7.222 2.172,7.828 2.778,8.326 3.469,8.696 4.22,8.923 5,9
  region: 68.78,8.923 69.531,8.696 70.222,8.326 70.828,7.828 71.326,7.222 71.696,6.531 71.923,5.78 72,5 71.923,4.22 71.696,3.469 71.326,2.778 70.828,2.172 70.222,1.674 69.531,1.304 68.78,1.077 68,1 67.22,1.077 66.469,1.304 65.778,1.674 65.172,2.172 64.674,2.778 64.304,3.469 64.077,4.22 64,5 64.077,5.78 64.304,6.531 64.674,7.222 65.172,7.828 65.778,8.326 66.469,8.696 67.22,8.923 68,9
  region: 5.78,58.923 6.531,58.696 7.222,58.326 7.828,57.828 8.326,57.222 8.696,56.531 8.923,55.78 9,55 8.923,54.22 8.696,53.469 8.326,52.778 7.828,52.172 7.222,51.674 6.531,51.304 5.78,51.077 5,51 4.22,51.077 3.469,51.304 2.778,51.674 2.172,52.172 1.674,52.778 1.304,53.469 1.077,54.22 1,55 1.077,55.78 1.304,56.531 1.674,57.222 2.172,57.828 2.778,58.326 3.469,58.696 4.22,58.923 5,59
Edge.Cuts:
  lines w0: 0,0 90,0 90,60 0,60 0,0
  lines w0.254: 0,0 90,0 90,60 0,60 0,0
